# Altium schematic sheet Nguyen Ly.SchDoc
size A
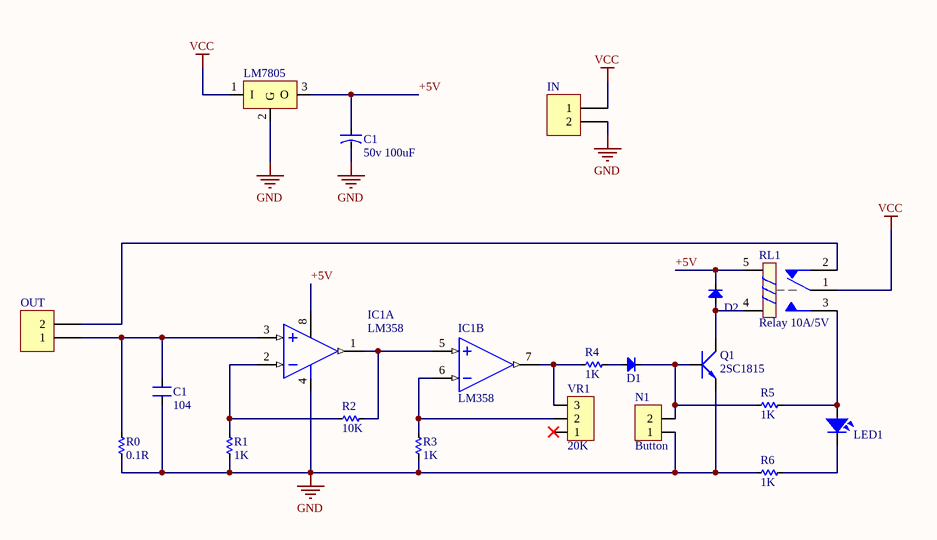
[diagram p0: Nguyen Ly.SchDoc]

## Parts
(Parts that share a designator on the sheet are numbered #1, #2 ... from top to bottom, then left to right.)
C1#1  50v 100uF  [CA-ALU-5L]
C1#2  104  [CN1.5]
D1  Diode  [DIO-1A]  (value not drawn)
D2  Diode  [DIO-1A]  (value not drawn)
IC1  LM358  [DIP8]  (parts A,B of 2)
IN  (no value)  [KF2-5.08]
LED1  LED  [LED-5-BLUE]  (value not drawn)
LM7805  LM78xx  [TO220-123]  (value not drawn)
N1  Button  [Header2]
OUT  (no value)  [KF2-5.08]
Q1  2SC1815  [TO92-123]
R0  0.1R  [RES-2W]
R1  1K  [RES-1/4W]
R2  10K  [RES-1/4W]
R3  1K  [RES-1/4W]
R4  1K  [RES-1/4W]
R5  1K  [RES-1/4W]
R6  1K  [RES-1/4W]
RL1  Relay 10A/5V  [RELAY 5]
VR1  20K  [Header3]

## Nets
GND: C1#1.2 C1#2.1 IC1.4(-V) IN.2 LM7805.2(G) N1.1 Q1.1(E) R0.2 R1.2 R3.2 R6.2
VCC: IN.1 LM7805.1(I) RL1.1
+5V: C1#1.1 D2.2(K) IC1.8(+V) LM7805.3(O) RL1.5
NetC1#2_2: C1#2.2 IC1.3(IN+) OUT.1 R0.1
NetD1_1: D1.1(A) R4.2
NetD1_2: D1.2(K) N1.2 Q1.3(B) R5.2
NetD2_1: D2.1(A) Q1.2(C) RL1.4
NetIC1_1: IC1.1(OUT) IC1.5(IN+) R2.2
NetIC1_2: IC1.2(IN-) R1.1 R2.1
NetIC1_6: IC1.6(IN-) R3.1 VR1.2
NetIC1_7: IC1.7(OUT) R4.1 VR1.3
NetLED1_1: LED1.1 R5.1 RL1.3
NetLED1_2: LED1.2 R6.1
NetOUT_2: OUT.2 RL1.2

Not connected (* = marked no-connect by the designer): VR1 1*

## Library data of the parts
C1#1 = CN-ALU-DIP: Capacitor (Semiconductor SIM Model); Value: 104
C1#2 = CN: Value: 33pF
D1 D2 = Diode: Default Diode; Code - JEDEC: DO-214-AB; Value: 1N5007
IC1 = LM358: Low-Power Dual Operational Amplifier
IN OUT = KF2: Manufacturer: Würth Elektronik eiSos GmbH; partNo: 691103110002; ComponentLink1 Description: Manufacturer; ComponentLink2 Description: Datasheet; NoPins: 2
LED1 = LED: LED Single colour Green and Red; Value: LED 3 ly Single Colour
LM7805 = LM78xx: Positive Voltage Regulator; Note: Tab is connected to pin 3 (GND).
N1 = Header2: Header IDC, 2 x 1 Pin Vertical 2.54mm Pitch (Non-Boxed, Male); Manufacturer: W¨¹rth Elektronik eiSos GmbH; partNo: 613002143121; ComponentLink1 Description: Manufacturer; ComponentLink2 Description: Datasheet; NoPins: 02
Q1 = 2SC1815: NPN 600mW, ECB; Value: C1815
R0-R6 = Res: Manufacturer: Generic Components; Class: Passive; SubClass: R
RL1 = Relay 5: Relay SPDT,10A - 12VDC 5 Pin; Value: Relay SPDT, 10A, 12V
VR1 = Header3: Header IDC, 3 x 1 Pin Vertical 2.54mm Pitch (Non-Boxed, Male); Manufacturer: W¨¹rth Elektronik eiSos GmbH; partNo: 613002143121; ComponentLink1 Description: Manufacturer; ComponentLink2 Description: Datasheet; NoPins: 02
